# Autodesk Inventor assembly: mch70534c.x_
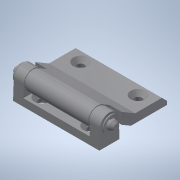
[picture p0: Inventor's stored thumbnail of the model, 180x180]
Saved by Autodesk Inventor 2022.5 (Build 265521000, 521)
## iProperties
Part Number: mch70534c.x_
Material: 一般
Document SubType Name: Assembly
Designer: ImaoCorp
Sending System: SOLIDWORKS 2017-2017317
MC: AMD64
MC_MODEL: Intel64 Family 6 Model 60 Stepping 3, GenuineIntel
OS: Windows_NT
FRU: Parasolid Version 29.0, build 201,  4-17-2017
FORMAT: text
GUISE: transmit
KEY: mch70534c
FILE: mch70534c.x_t
DATE: Fri Jul 26 11:41:39 2019
Author: ImaoCorp
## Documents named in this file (4)
- X:\14_SW2022-Inv2022\00_全2023-1023新製品(TCC)まで\m\mch70534c\MCH70534C.iam
- X:\14_SW2022-Inv2022\00_全2023-1023新製品(TCC)まで\m\mch70534c\mch70534c_01.ipt
- X:\14_SW2022-Inv2022\00_全2023-1023新製品(TCC)まで\m\mch70534c\mch70534c_02.ipt
- X:\14_SW2022-Inv2022\00_全2023-1023新製品(TCC)まで\m\mch70534c\mch70534c_03.ipt
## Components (3 placed, 3 different names)
1. mch70534c_01
2. mch70534c_02
3. mch70534c_03
